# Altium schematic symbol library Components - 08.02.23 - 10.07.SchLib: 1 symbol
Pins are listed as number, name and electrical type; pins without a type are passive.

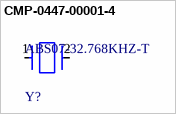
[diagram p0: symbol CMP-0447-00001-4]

## CMP-0447-00001-4
designator Y?, comment ABS07-32.768KHZ-T
Crystal 32.768kHz ±20ppm (Tol) 12.5pF FUND 70kΩ 2-Pin CSMD T/R; ESR (Equivalent Series Resistance): 70kR
footprint FP-ABS07-MFG
pins: 1, 2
